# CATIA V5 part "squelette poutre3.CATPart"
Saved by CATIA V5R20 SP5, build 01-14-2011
Part number: squelette poutre3
Publications: "L_poutre3", "Esquisse.1", "Point.15", "Droite.3"
Bounding box of the stored display mesh (mm): x 100 to 100, y 280 to 1373.95, z 309.845 to 550
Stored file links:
  F:\iao fini\squelette poutre3.CATPart
  F:\iao fini\iao-finipbgliss.CATProduct
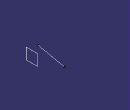
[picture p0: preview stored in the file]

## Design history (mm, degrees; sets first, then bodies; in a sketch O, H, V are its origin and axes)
Parameters
  L_poutre3 = 1120 mm
Set1
  Point1 "A": linked copy from another document
  Point2 "Abis": linked copy from another document
  Plane1 "Plan CD": linked copy from another document
  Line1: linked copy from another document
  Line2: linked copy from another document
Body1 (main body)
  Set2
    Plane2 "Plan3": type Offset, RefPlane yz-plane, Offset 100
    Point3: type OnPlane, Support Plane2, RefPoint Point2, H 0, V 0, Direction (0, 1, 0)
    Point4: type OnPlane, Support Plane2, H 1368.221, V 311.103, Direction (0, 1, 0)
    Line3: type PtPt, FirstPoint Point4, SecondPoint Point3, Support Plane2, Start 410, End 622
    Line4: type PtDir, RefPoint Point3, Direction Line3, Support Plane2, Start 0, End -1120 {= -L_poutre3}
